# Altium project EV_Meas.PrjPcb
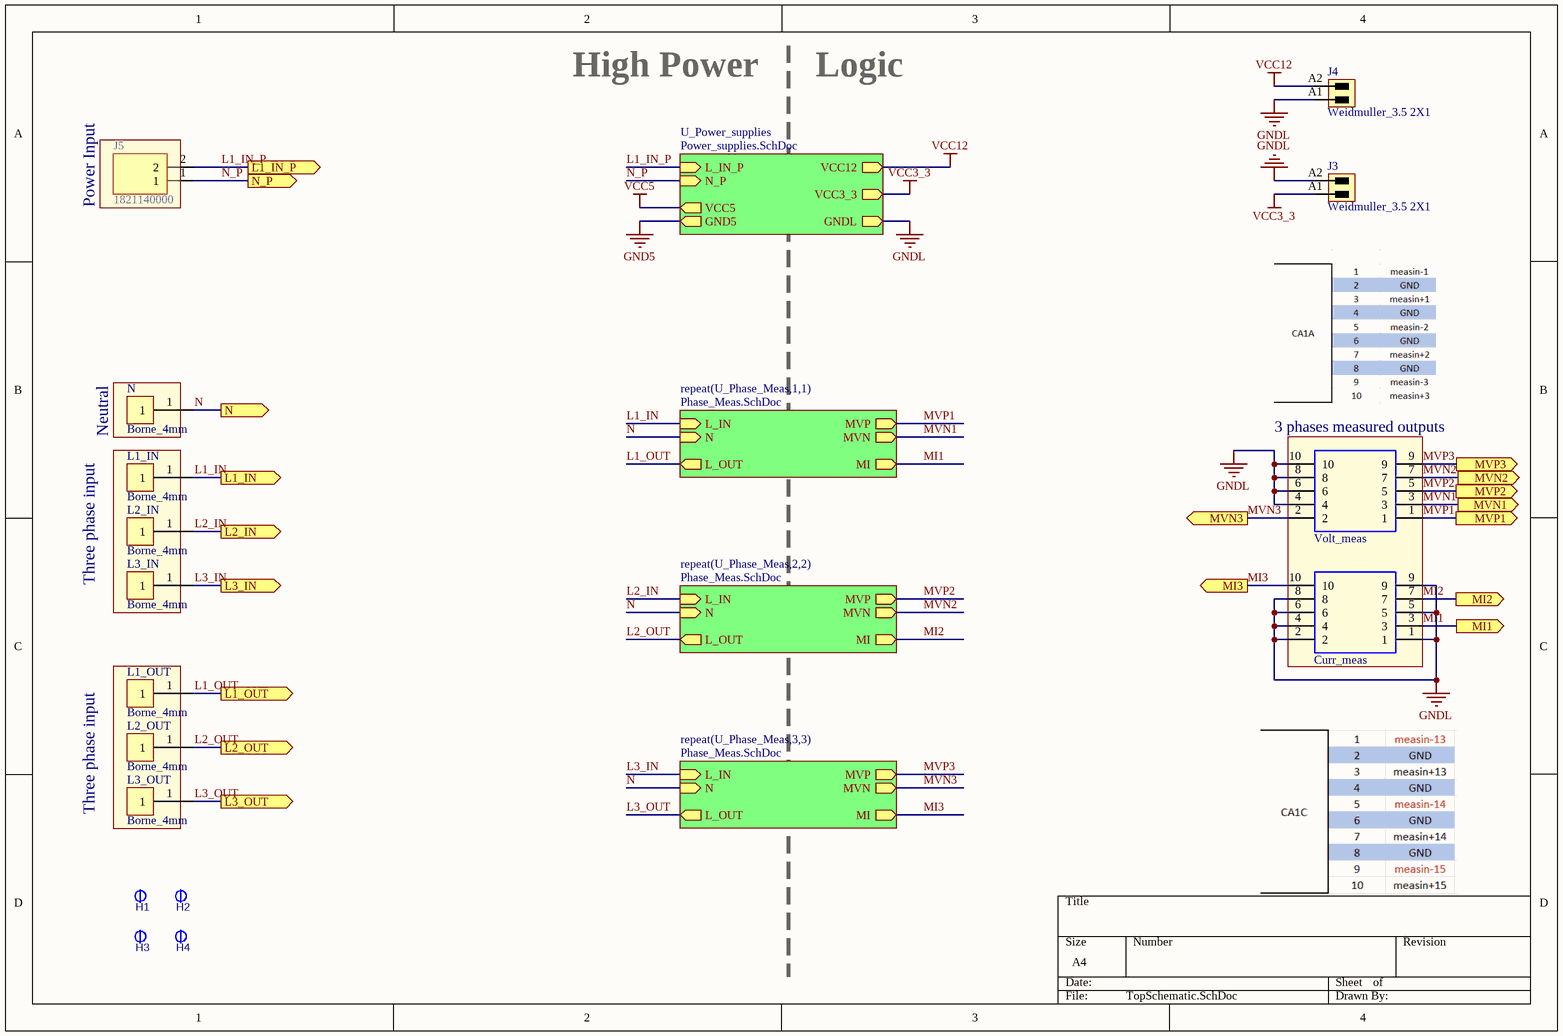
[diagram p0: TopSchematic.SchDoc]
3 sheets, 79 parts. Net scope: hierarchical (ports join the sheet entries above them; power ports are global).
Board file: EV_Meas.PcbDoc
Sheets:
  TopSchematic.SchDoc
    U_Phase_Meas1 = Phase_Meas.SchDoc
    U_Phase_Meas2 = Phase_Meas.SchDoc
    U_Phase_Meas3 = Phase_Meas.SchDoc
    U_Power_supplies = Power_supplies.SchDoc

## Sheet TopSchematic.SchDoc
size A4; SheetNumber: 1; SheetTotal: 3

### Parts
Curr_meas  Molex MILLI-GRID SMD 5x2 2mm 87832-1020  [87832-1020r]  (value not drawn)
H1  3.2  [HOLE_3.2_NP]  (value not drawn)  (no BOM)
H2  3.2  [HOLE_3.2_NP]  (value not drawn)  (no BOM)
H3  3.2  [HOLE_3.2_NP]  (value not drawn)  (no BOM)
H4  3.2  [HOLE_3.2_NP]  (value not drawn)  (no BOM)
J3  Weidmuller_3.5 2X1  [SL_3_50_90G_02]
J4  Weidmuller_3.5 2X1  [SL_3_50_90G_02]
J5  1821140000  [1821140000]
L1_IN  Borne_4mm  [Borne4mm_WE]
L1_OUT  Borne_4mm  [Borne4mm_WE]
L2_IN  Borne_4mm  [Borne4mm_WE]
L2_OUT  Borne_4mm  [Borne4mm_WE]
L3_IN  Borne_4mm  [Borne4mm_WE]
L3_OUT  Borne_4mm  [Borne4mm_WE]
N  Borne_4mm  [Borne4mm_WE]
Volt_meas  Molex MILLI-GRID SMD 5x2 2mm 87832-1020  [87832-1020r]  (value not drawn)

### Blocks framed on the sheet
Power Input: J5
Neutral: N

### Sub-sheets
repeat(U_Phase_Meas,1,1) = Phase_Meas.SchDoc: L_IN (in), N (in), L_OUT (out), MVP (out), MVN (out), MI (out)
repeat(U_Phase_Meas,2,2) = Phase_Meas.SchDoc: L_IN (in), N (in), L_OUT (out), MVP (out), MVN (out), MI (out)
repeat(U_Phase_Meas,3,3) = Phase_Meas.SchDoc: L_IN (in), N (in), L_OUT (out), MVP (out), MVN (out), MI (out)
U_Power_supplies = Power_supplies.SchDoc: N_P (in), L_IN_P (in), VCC5 (out), GND5 (out), VCC3_3 (out), GNDL (out), VCC12 (out)

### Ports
L1_IN (out), L1_IN_P (out), L1_OUT (out), L2_IN (out), L2_OUT (out), L3_IN (out), L3_OUT (out), MI1 (out), MI2 (out), MI3 (out), MVN1 (out), MVN2 (out), MVN3 (out), MVP1 (out), MVP2 (out), MVP3 (out), N (out), N_P (out)

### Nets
GNDL: Curr_meas.1 Curr_meas.2 Curr_meas.4 Curr_meas.5 Curr_meas.6 Curr_meas.8 Curr_meas.9 J3.A2 J4.A1 Volt_meas.4 Volt_meas.6 Volt_meas.8 Volt_meas.10 ; sheet U_Power_supplies/GNDL
VCC3_3: J3.A1 ; sheet U_Power_supplies/VCC3_3
VCC12: J4.A2 ; sheet U_Power_supplies/VCC12
L1_IN: L1_IN.1 ; port L1_IN, sheet repeat(U_Phase_Meas,1,1)/L_IN
L1_IN_P: J5.2 ; port L1_IN_P, sheet U_Power_supplies/L_IN_P
L1_OUT: L1_OUT.1 ; port L1_OUT, sheet repeat(U_Phase_Meas,1,1)/L_OUT
L2_IN: L2_IN.1 ; port L2_IN, sheet repeat(U_Phase_Meas,2,2)/L_IN
L2_OUT: L2_OUT.1 ; port L2_OUT, sheet repeat(U_Phase_Meas,2,2)/L_OUT
L3_IN: L3_IN.1 ; port L3_IN, sheet repeat(U_Phase_Meas,3,3)/L_IN
L3_OUT: L3_OUT.1 ; port L3_OUT, sheet repeat(U_Phase_Meas,3,3)/L_OUT
MI1: Curr_meas.3 ; port MI1, sheet repeat(U_Phase_Meas,1,1)/MI
MI2: Curr_meas.7 ; port MI2, sheet repeat(U_Phase_Meas,2,2)/MI
MI3: Curr_meas.10 ; port MI3, sheet repeat(U_Phase_Meas,3,3)/MI
MVN1: Volt_meas.3 ; port MVN1, sheet repeat(U_Phase_Meas,1,1)/MVN
MVN2: Volt_meas.7 ; port MVN2, sheet repeat(U_Phase_Meas,2,2)/MVN
MVN3: Volt_meas.2 ; port MVN3, sheet repeat(U_Phase_Meas,3,3)/MVN
MVP1: Volt_meas.1 ; port MVP1, sheet repeat(U_Phase_Meas,1,1)/MVP
MVP2: Volt_meas.5 ; port MVP2, sheet repeat(U_Phase_Meas,2,2)/MVP
MVP3: Volt_meas.9 ; port MVP3, sheet repeat(U_Phase_Meas,3,3)/MVP
N: N.1 ; port N, sheet repeat(U_Phase_Meas,1,1)/N, sheet repeat(U_Phase_Meas,2,2)/N, sheet repeat(U_Phase_Meas,3,3)/N
N_P: J5.1 ; port N_P, sheet U_Power_supplies/N_P

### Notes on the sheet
- High Power
- Logic
- (near Volt_meas) 3 phases measured outputs
- Three phase input

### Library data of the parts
Curr_meas Volt_meas = Molex MILLI-GRID SMD 5x2 2mm 87832-1020: 87832-1020 -  Connecteur fil-à-carte, 2 mm, 10 Contact(s), Embase, Milli-Grid 87832 Series, Montage CMS; Manufacturer Part Number: 0878321014; Number of Positions: 10; Connector Type: Male Pin; Row Spacing: 0.079inch
H1-H4 = HOLE_3.2_NP: Hole 3.2 unplated
J3 J4 = Weidmuller_3.5 2X1: Series BL/SL 3.50 2-Pin; Manufacturer P/N: SL 3.50/02/90G
J5 = 1821140000: Connector; Manufacturer_Name: Weidmuller
L1_IN L1_OUT L2_IN L2_OUT L3_IN L3_OUT N = Borne_4mm_WE: Borne 4mm avec connecteur WE; Manufacturer P/N: 7460305

## Sheet Phase_Meas.SchDoc
size A4; SheetNumber: 3; SheetTotal: 3; Value: 0.1uF
Used 3 times, as channels U_Phase_Meas1, U_Phase_Meas2, U_Phase_Meas3. Parts and nets are listed once, with the designators drawn on the sheet.
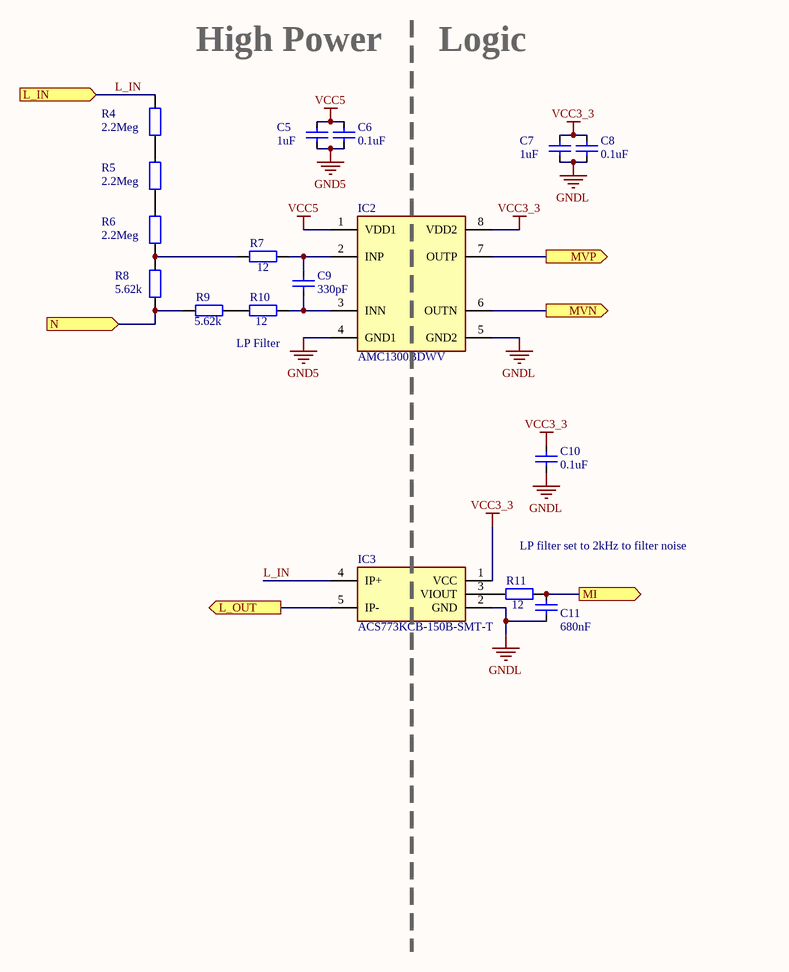
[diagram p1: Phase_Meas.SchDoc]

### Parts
C5  value 1uF  [C-0603]  (hidden comment: C-SMD-0603)
C6  value 0.1uF  [C-0603]  (hidden comment: C-SMD-0603)
C7  value 1uF  [C-0603]  (hidden comment: C-SMD-0603)
C8  value 0.1uF  [C-0603]  (hidden comment: C-SMD-0603)
C9  value 330pF  [C-0805]  (hidden comment: C-SMD-0805)
C10  value 0.1uF  [C-0603]  (hidden comment: C-SMD-0603)
C11  value 680nF  [C-0603]  (hidden comment: C-SMD-0603)
IC2  AMC1300BDWV  [SOIC127P1150X280-8N]
IC3  ACS773KCB-150B-SMT-T  [ACS772LCB050BSMTT]
R4  value 2.2Meg  [R-0805]  (hidden comment: R-SMD-0805)
R5  value 2.2Meg  [R-0805]  (hidden comment: R-SMD-0805)
R6  value 2.2Meg  [R-0805]  (hidden comment: R-SMD-0805)
R7  value 12  [R-0603]  (hidden comment: R-SMD-0603)
R8  value 5.62k  [R-1206]  (hidden comment: R-SMD-1206)
R9  value 5.62k  [R-1206]  (hidden comment: R-SMD-1206)
R10  value 12  [R-0603]  (hidden comment: R-SMD-0603)
R11  value 12  [R-0603]  (hidden comment: R-SMD-0603)

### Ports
L_IN (in, see TopSchematic[2B]), L_OUT (out, see TopSchematic[2B]), MI (out, see TopSchematic[3B]), MVN (out, see TopSchematic[3B]), MVP (out, see TopSchematic[3B]), N (in, see TopSchematic[2B])

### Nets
GND5: C5.1 C6.1 IC2.4(GND1)
GNDL: C7.1 C8.1 C10.1 C11.1 IC2.5(GND2) IC3.2(GND)
VCC3_3: C7.2 C8.2 C10.2 IC2.8(VDD2) IC3.1(VCC)
VCC5: C5.2 C6.2 IC2.1(VDD1)
L_IN: IC3.4(IP+) R4.1 ; port L_IN
L_OUT: IC3.5(IP-) ; port L_OUT
MI: C11.2 R11.2 ; port MI
MVN: IC2.6(OUTN) ; port MVN
MVP: IC2.7(OUTP) ; port MVP
N: R8.1 R9.1 ; port N
NetC9_1: C9.1 IC2.3(INN) R10.2
NetC9_2: C9.2 IC2.2(INP) R7.2
NetIC3_3: IC3.3(VIOUT) R11.1
NetR4_2: R4.2 R5.1
NetR5_2: R5.2 R6.1
NetR6_2: R6.2 R7.1 R8.2
NetR9_2: R9.2 R10.1

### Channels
U_Phase_Meas1: designators end in A; ports L_IN=L1_IN L_OUT=L1_OUT MI=MI1 MVN=MVN1 MVP=MVP1 N=N
U_Phase_Meas2: designators end in B; ports L_IN=L2_IN L_OUT=L2_OUT MI=MI2 MVN=MVN2 MVP=MVP2 N=N
U_Phase_Meas3: designators end in C; ports L_IN=L3_IN L_OUT=L3_OUT MI=MI3 MVN=MVN3 MVP=MVP3 N=N

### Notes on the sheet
- High Power
- Logic
- LP Filter
- LP filter set to 2kHz to filter noise

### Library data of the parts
C5-C8 C10 C11 = CMP-003-000008-1: Multilayer Ceramic Capacitors MLCC; Mfr. Part No.: GRM18...; Manufacturer: Murata Electronics; Order-Code: 81-GRM18...
C9 = CMP-003-000005-1: Multilayer Ceramic Capacitors MLCC; Mfr. Part No.: GRM21*; Manufacturer: Murata Electronics; Order-Code: 81-GRM21...
IC2 = AMC1300BDWV: Integrated Circuit; Manufacturer_Name: Texas Instruments
IC3 = ACS773KCB-150B-SMT-T: Integrated Circuit; Manufacturer_Name: Allegro Microsystems
R4-R6 = CMP-013-000007-1: Thin Film Resistors - SMD  0.1W  1%; Manufacturer: Vishay / Beyschlag; Mfr. Part No.: MCT06030C*; Order-Code: BFH-Lager
R7 R10 R11 = CMP-013-000006-1: Thin Film Resistors - SMD  0.1W  1%; Manufacturer: Vishay / Beyschlag; Mfr. Part No.: MCU08050C*; Order-Code: BFH-Lager
R8 R9 = CMP-013-000008-1: Thin Film Resistors - SMD  0.1W  1%; Manufacturer: Vishay / Beyschlag; Mfr. Part No.: MCA12060C; Order-Code: BFH-Lager

## Sheet Power_supplies.SchDoc
size A4; SheetNumber: 2; SheetTotal: 3
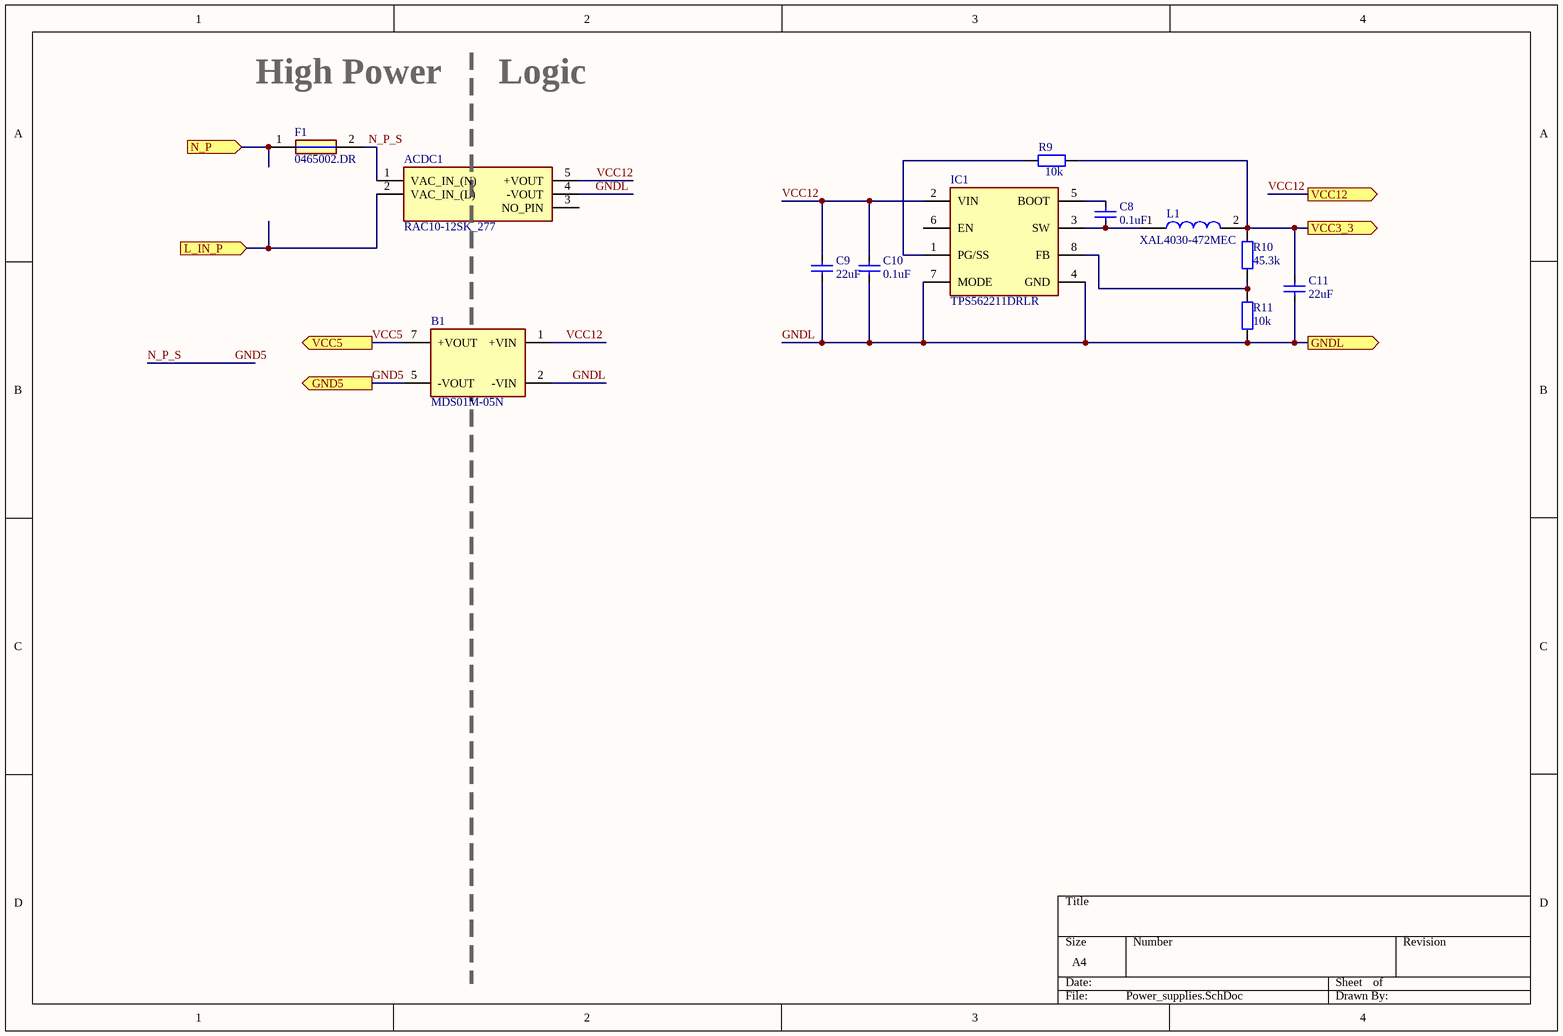
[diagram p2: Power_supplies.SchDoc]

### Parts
ACDC1  RAC10-12SK_277  [RAC1005SK277]
B1  MDS01M-05N  [MDS01M05N]
C8  value 0.1uF  [C-0603]  (hidden comment: C-SMD-0603)
C9  value 22uF  [C-0805]  (hidden comment: C-SMD-0805)
C10  value 0.1uF  [C-0603]  (hidden comment: C-SMD-0603)
C11  value 22uF  [C-0805]  (hidden comment: C-SMD-0805)
F1  0465002.DR  [FUSC12145X450N]
IC1  TPS562211DRLR  [SOTFL50P160X60-8N]
L1  XAL4030-472MEC  [XAL4030472MEC]
R9  value 10k  [R-0603]  (hidden comment: R-SMD-0603)
R10  value 45.3k  [R-0603]  (hidden comment: R-SMD-0603)
R11  value 10k  [R-0603]  (hidden comment: R-SMD-0603)

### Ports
GND5 (out, see TopSchematic[2A]), GNDL (out, see TopSchematic[3A]), L_IN_P (in, see TopSchematic[2A]), N_P (in, see TopSchematic[2A]), VCC3_3 (out, see TopSchematic[3A]), VCC5 (out, see TopSchematic[2A]), VCC12 (out, see TopSchematic[3A])

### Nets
GND5: ACDC1.1(VAC_IN_(N)) B1.5(-VOUT) F1.2 ; port GND5  [also labelled N_P_S]
GNDL: ACDC1.4(-VOUT) B1.2(-VIN) C9.1 C10.1 C11.1 IC1.4(GND) IC1.7(MODE) R11.1 ; port GNDL
VCC3_3: C11.2 L1.2 R9.2 R10.2 ; port VCC3_3
VCC5: B1.7(+VOUT) ; port VCC5
VCC12: ACDC1.5(+VOUT) B1.1(+VIN) C9.2 C10.2 IC1.2(VIN) ; port VCC12
L1_IN_P: ACDC1.2(VAC_IN_(L)) ; port L_IN_P
N_P: F1.1 ; port N_P
NetC8_1: C8.1 IC1.3(SW) L1.1
NetC8_2: C8.2 IC1.5(BOOT)
NetIC1_1: IC1.1(PG/SS) R9.1
NetIC1_8: IC1.8(FB) R10.1 R11.2

Not connected (* = marked no-connect by the designer): ACDC1 3(NO_PIN); IC1 6(EN)

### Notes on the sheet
- High Power
- Logic

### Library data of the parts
ACDC1 = RAC10-12SK_277: Power Supply; Manufacturer_Name: RECOM Power; Manufacturer_Part_Number: RAC10-12SK/277
B1 = MDS01M-05N: Isolated DC/DC Converters - Through Hole 1W 12Vin 5Vout 20-200mA SIP7 Medical Unregulated; Manufacturer_Name: Mean Well; Geometry.Height: 12mm
C8 C10 = CMP-003-000008-1: as C5 on sheet Phase_Meas
C9 C11 = CMP-001-00107-1: Multilayer Ceramic Capacitors MLCC; Manufacturer: Murata Electronics; Mfr. Part No.: GRM21*; Order-Code: 81-GRM21...
F1 = 0465002.DR: Fuse; Manufacturer_Name: LITTELFUSE
IC1 = TPS562211DRLR: Integrated Circuit; Manufacturer_Name: Texas Instruments
L1 = XAL4030-472MEC: Inductor; Manufacturer_Name: COILCRAFT
R9-R11 = CMP-013-000006-1: as R7 on sheet Phase_Meas

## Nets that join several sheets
GND5: U_Phase_Meas1 (C5A.1 C6A.1 IC2A.4), U_Phase_Meas2 (C5B.1 C6B.1 IC2B.4), U_Phase_Meas3 (C5C.1 C6C.1 IC2C.4), Power_supplies (ACDC1.1 B1.5 F1.2)
GNDL: TopSchematic (13 pins), U_Phase_Meas1 (6 pins), U_Phase_Meas2 (6 pins), U_Phase_Meas3 (6 pins), Power_supplies (8 pins)
VCC3_3: TopSchematic (J3.A1), U_Phase_Meas1 (5 pins), U_Phase_Meas2 (5 pins), U_Phase_Meas3 (5 pins), Power_supplies (C11.2 L1.2 R9.2 R10.2)
VCC5: U_Phase_Meas1 (C5A.2 C6A.2 IC2A.1), U_Phase_Meas2 (C5B.2 C6B.2 IC2B.1), U_Phase_Meas3 (C5C.2 C6C.2 IC2C.1), Power_supplies (B1.7)
VCC12: TopSchematic (J4.A2), Power_supplies (5 pins)
L1_IN: TopSchematic (L1_IN.1), U_Phase_Meas1 (IC3A.4 R4A.1)
L1_IN_P: TopSchematic (J5.2), Power_supplies (ACDC1.2)
L1_OUT: TopSchematic (L1_OUT.1), U_Phase_Meas1 (IC3A.5)
L2_IN: TopSchematic (L2_IN.1), U_Phase_Meas2 (IC3B.4 R4B.1)
L2_OUT: TopSchematic (L2_OUT.1), U_Phase_Meas2 (IC3B.5)
L3_IN: TopSchematic (L3_IN.1), U_Phase_Meas3 (IC3C.4 R4C.1)
L3_OUT: TopSchematic (L3_OUT.1), U_Phase_Meas3 (IC3C.5)
MI1: TopSchematic (Curr_meas.3), U_Phase_Meas1 (C11A.2 R11A.2)
MI2: TopSchematic (Curr_meas.7), U_Phase_Meas2 (C11B.2 R11B.2)
MI3: TopSchematic (Curr_meas.10), U_Phase_Meas3 (C11C.2 R11C.2)
MVN1: TopSchematic (Volt_meas.3), U_Phase_Meas1 (IC2A.6)
MVN2: TopSchematic (Volt_meas.7), U_Phase_Meas2 (IC2B.6)
MVN3: TopSchematic (Volt_meas.2), U_Phase_Meas3 (IC2C.6)
MVP1: TopSchematic (Volt_meas.1), U_Phase_Meas1 (IC2A.7)
MVP2: TopSchematic (Volt_meas.5), U_Phase_Meas2 (IC2B.7)
MVP3: TopSchematic (Volt_meas.9), U_Phase_Meas3 (IC2C.7)
N: TopSchematic (N.1), U_Phase_Meas1 (R8A.1 R9A.1), U_Phase_Meas2 (R8B.1 R9B.1), U_Phase_Meas3 (R8C.1 R9C.1)
N_P: TopSchematic (J5.1), Power_supplies (F1.1)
